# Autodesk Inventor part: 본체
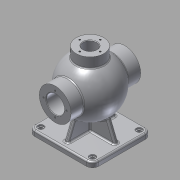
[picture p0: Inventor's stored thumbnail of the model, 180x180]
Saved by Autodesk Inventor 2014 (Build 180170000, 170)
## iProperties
Created: 2015-10
Part Number: 본체
Material: Aluminum 6061
Document SubType Name: Modeling
Designer: youjin08
Density: 2.71 g/cm^3
Appearance: Aluminum - Flat
Mass: 1509.57 g
Surface Area: 1153.7 cm^2
Volume: 557.037 cm^3
Author: youjin08
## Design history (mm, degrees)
sketch "Sketch1"
  geometry: L1 (-62.5, -57.5)-(62.5, -57.5); L2 (62.5, -57.5)-(62.5, 57.5); L3 (62.5, 57.5)-(-62.5, 57.5); L4 (-62.5, 57.5)-(-62.5, -57.5); L5 (-62.5, -57.5)-(62.5, 57.5); L6 (62.5, -57.5)-(-62.5, 57.5); 1 further point
  constraints: 12 end point, 2 midpoint, 2 parallel, 1 horizontal, 1 perpendicular
  dimensions: "d0" = 125 distance of L3.end L2.end; "d1" = 115 distance of L2.end L1.end
extrude "Extrusion1" new body sketch "Sketch1" distance "d2" = 10; taper "d3" = 0 deg
fillet "Fillet1" dims "d4" = 12
sketch "Sketch2"
  geometry: C1 r 6 at (-50.5, 45.5); C2 r 6 at (-50.5, -45.5); C3 r 6 at (50.5, 45.5); C4 r 6 at (50.5, -45.5); A1 r 12 centre (50.5, 45.5) between (62.5, 45.5) and (50.5, 57.5) reference; A2 r 12 centre (-50.5, 45.5) between (-50.5, 57.5) and (-62.5, 45.5) reference; A3 r 12 centre (-50.5, -45.5) between (-62.5, -45.5) and (-50.5, -57.5) reference; A4 r 12 centre (50.5, -45.5) between (50.5, -57.5) and (62.5, -45.5) reference; 1 further point
  constraints: 4 centre point, 4 coincident
  dimensions: "d5" = 12 diameter of C1; "d6" = 12 diameter of C2; "d7" = 12 diameter of C3; "d8" = 12 diameter of C4
extrude "Extrusion2" cut sketch "Sketch2" distance "d9" = 3; taper "d10" = 0 deg
sketch "Sketch3"
  geometry: C1 r 6 at (0, 0) reference; C2 r 6 at (0, 91) reference; C3 r 6 at (101, 91) reference; C4 r 6 at (101, 0) reference; C5 r 4 at (0, 0); C6 r 4 at (0, 91); C7 r 4 at (101, 91); C8 r 4 at (101, 0); 1 further point
  constraints: 4 centre point, 4 coincident
  dimensions: "d11" = 8 diameter of C5; "d12" = 8 diameter of C6; "d13" = 8 diameter of C7; "d14" = 8 diameter of C8
extrude "Extrusion3" cut sketch "Sketch3" stored distance "d15" = 3; taper "d16" = 0 deg
sketch "Sketch4"
  geometry: L1 (50.5, 57.5)-(-50.5, 57.5) reference; L2 (-62.5, 45.5)-(-62.5, -45.5) reference; L3 (-50.5, -57.5)-(50.5, -57.5) reference; L4 (62.5, -45.5)-(62.5, 45.5) reference; C1 r 6 at (50.5, 45.5) reference; C2 r 6 at (-50.5, 45.5) reference; C3 r 6 at (-50.5, -45.5) reference; C4 r 6 at (50.5, -45.5) reference; A1 r 12 centre (50.5, 45.5) between (62.5, 45.5) and (50.5, 57.5) reference; A2 r 12 centre (-50.5, 45.5) between (-50.5, 57.5) and (-62.5, 45.5) reference; A3 r 12 centre (-50.5, -45.5) between (-62.5, -45.5) and (-50.5, -57.5) reference; A4 r 12 centre (50.5, -45.5) between (50.5, -57.5) and (62.5, -45.5) reference; 1 further point
sketch "Sketch5"
  geometry: L1 (0, 32)-(0, 138); A1 r 53 centre (0, 85) between (0, 32) and (0, 138); 1 further point
  constraints: 2 end point, 2 point on circle, 1 centre point, 1 vertical alignment
  dimensions: "d17" = 53 radius of A1; "d18" = 85 distance of point (0, 0) A1.centre
revolve "Revolution1" sketch "Sketch5" stored, may be unused: angle "d19" = 90 deg
sketch "Sketch7"
  geometry: C1 r 53 at (0, 85) reference; C2 r 31 at (0, 85); 1 further point
  constraints: 1 centre point, 1 coincident
  dimensions: "d20" = 62 diameter of C2
extrude "Extrusion4" join sketch "Sketch7" stored distance "d21" = 136; taper "d22" = 0 deg
sketch "Sketch8"
  geometry: L1 (0, 42)-(0, 128); C1 r 53 at (0, 85) reference; A1 r 43 centre (0, 85) between (0, 42) and (0, 128); 1 further point
  constraints: 2 end point, 2 point on circle, 1 centre point, 1 coincident, 1 vertical
  dimensions: "d23" = 43 radius of A1
revolve "Revolution2" sketch "Sketch8" stored, may be unused: angle "d24" = 90 deg
sketch "Sketch9"
  geometry: C1 r 31 at (0, 0) reference; C2 r 17.5 at (0, 0); 1 further point
  constraints: 1 centre point, 1 coincident
  dimensions: "d25" = 35 diameter of C2
extrude "Extrusion5" cut sketch "Sketch9" stored distance "d26" = 136; taper "d27" = 0 deg
workplane "Work Plane1"
sketch "Sketch10"
  geometry: C1 r 27 at (0, 0); 1 further point
  constraints: 1 centre point, 1 coincident
  dimensions: "d29" = 54 diameter of C1
extrude "Extrusion6" join sketch "Sketch10" stored distance "d30" = 136; taper "d31" = 0 deg
sketch "Sketch11"
  geometry: C1 r 27 at (0, 0) reference; C2 r 13 at (0, 0)
  constraints: 1 centre point, 1 coincident
  dimensions: "d32" = 26 diameter of C2
extrude "Extrusion7" cut sketch "Sketch11" stored distance "d33" = 136; taper "d34" = 0 deg
sketch "Sketch13"
  geometry: C1 r 17.5 at (0, 0) reference; C2 r 31 at (0, 0) reference; A1 r 22.5 centre (0, 0) between (0, 22.5) and (-22.5, 0); 3 further points
  constraints: 4 point on circle, 2 horizontal alignment, 2 vertical alignment, 1 centre point, 1 coincident
  dimensions: "d35" = 45 diameter of A1
hole "Hole1" sketch "Sketch13" at (0, 22.5), (-22.5, 0), (0, -22.5), (22.5, 0) diameter "d36" = 3.242; stored, may be unused: countersink angle "d40" = 90 deg, drill point angle "d42" = 118 deg; dims "d37" = 12, "d38" = 4, "d39" = 2, "d41" = 15
sketch "Sketch15"
  geometry: C1 r 17.5 at (0, 0) reference; C2 r 31 at (0, 0) reference; A1 r 24 centre (0, 0) between (0, 24) and (-24, 0); 3 further points
  constraints: 4 point on circle, 2 horizontal alignment, 2 vertical alignment, 1 centre point, 1 coincident
  dimensions: "d43" = 48 diameter of A1
sketch "Sketch16"
  geometry: C1 r 13 at (0, 0) reference; C2 r 27 at (0, 0) reference; A1 r 20 centre (0, 0) between (0, 20) and (20, 0); 2 further points
  constraints: 4 point on circle, 2 horizontal alignment, 2 vertical alignment, 1 centre point, 1 coincident
  dimensions: "d51" = 40 diameter of A1
hole "Hole3" sketch "Sketch16" at (0, 20), (-20, 0), (0, -20), (20, 0) diameter "d52" = 3.242; stored, may be unused: countersink angle "d56" = 90 deg, drill point angle "d58" = 118 deg; dims "d53" = 9, "d54" = 4, "d55" = 2, "d57" = 11
sketch "Sketch17"
  geometry: L1 (-56.5, 10)-(-44.5, 10) reference; L2 (-62.5, 10)-(-50.5, 10) reference; L3 (50.5, 10)-(62.5, 10) reference; L4 (44.5, 10)-(56.5, 10) reference; L5 (-37.379, 47.426)-(-52.5, 10); L6 (37.379, 47.426)-(52.5, 10); L7 (-62.5, 0)-(-62.5, 10) reference; L8 (62.5, 10)-(62.5, 0) reference; A1 r 53 centre (0, 85) between (-27, 130.607) and (27, 130.607) reference; A2 r 53 centre (0, 85) between (-27, 130.607) and (27, 130.607) reference; 1 further point
  constraints: 4 end point, 2 point on circle, 2 point on line
  dimensions: "d59" = 22 deg angle of L7 L5; "d60" = 10 distance from line of L7 L5.end; "d61" = 22 deg angle of L8 L6; "d62" = 10 distance from line of L8 L6.end
sketch "Sketch18"
  geometry: L1 (50.5, 57.5)-(-50.5, 57.5) reference; L2 (-62.5, 45.5)-(-62.5, -45.5) reference; L3 (-50.5, -57.5)-(50.5, -57.5) reference; L4 (62.5, -45.5)-(62.5, 45.5) reference; L5 (-4, -45.5)-(4, -45.5); L6 (4, -45.5)-(4, 45.5); L7 (4, 45.5)-(-4, 45.5); L8 (-4, 45.5)-(-4, -45.5); L9 (-4, -45.5)-(4, 45.5); L10 (4, -45.5)-(-4, 45.5); L11 (-50.5, -4)-(50.5, -4); L12 (50.5, -4)-(50.5, 4); L13 (50.5, 4)-(-50.5, 4); L14 (-50.5, 4)-(-50.5, -4); L15 (-50.5, -4)-(50.5, 4); L16 (50.5, -4)-(-50.5, 4); C1 r 6 at (50.5, -45.5) reference; C2 r 6 at (-50.5, -45.5) reference; C3 r 6 at (-50.5, 45.5) reference; C4 r 6 at (50.5, 45.5) reference; A1 r 12 centre (50.5, 45.5) between (62.5, 45.5) and (50.5, 57.5) reference; A2 r 12 centre (-50.5, 45.5) between (-50.5, 57.5) and (-62.5, 45.5) reference; A3 r 12 centre (-50.5, -45.5) between (-62.5, -45.5) and (-50.5, -57.5) reference; A4 r 12 centre (50.5, -45.5) between (50.5, -57.5) and (62.5, -45.5) reference; 1 further point
  constraints: 24 end point, 4 midpoint, 4 parallel, 2 horizontal, 2 perpendicular
  dimensions: "d63" = 8 distance of L7.end L6.end; "d64" = 91 distance of L6.end L5.end; "d65" = 101 distance of L13.end L12.end; "d66" = 8 distance of L12.end L11.end
fillet "Fillet4" dims "d77" = 3
workplane "Work Plane2"
sketch "Sketch20"
  geometry: C1 r 17.5 at (0, 0) reference; C2 r 18.5 at (0, 0); 1 further point
  constraints: 1 centre point, 1 coincident
  dimensions: "d79" = 37 diameter of C2
sketch "Sketch21"
  geometry: 1 further point
extrude "Extrusion10" join sketch "Sketch20" distance "d80" = 1.75; taper "d81" = 0 deg
sketch "Sketch22"
  geometry: 1 further point
sketch "Sketch23"
  geometry: C1 r 17.5 at (0, 0) reference; C2 r 18.5 at (0, 0); 1 further point
  constraints: 1 centre point, 1 coincident
  dimensions: "d82" = 37 diameter of C2
extrude "Extrusion11" cut sketch "Sketch23" distance "d83" = 1.75; taper "d84" = 0 deg
hole "Hole4" sketch "Sketch15" diameter "d85" = 3.242; stored, may be unused: countersink angle "d89" = 90 deg, drill point angle "d91" = 118 deg; dims "d86" = 16, "d87" = 4, "d88" = 2, "d90" = 19
chamfer "Chamfer1" distance "d92" = 1; stored, may be unused: second distance "d93" = 2, angle "d94" = 45 deg
workplane "Work Plane3"
sketch "Sketch24"
  geometry: 1 further point
sketch "Sketch25"
  geometry: L1 (-27, 150)-(27, 150) reference; L2 (-27, 150)-(-27, 132.286) reference; 2 further points
  constraints: 1 other
  dimensions: "d96" = 10 distance from line of point (0, 140) L1; "d97" = 27 distance from line of L2 point (0, 140)
emboss "Emboss1" sketch "Sketch25" dims "d98" = 0.5, "d99" = 0
fillet "Fillet5" dims "d100" = 3
sketch "Sketch26"
  geometry: L1 (-4, -4)-(4, -4); L2 (4, -4)-(4, 4); L3 (4, 4)-(-4, 4); L4 (-4, 4)-(-4, -4); L5 (-4, -4)-(4, 4); L6 (4, -4)-(-4, 4); 1 further point
  constraints: 12 end point, 2 midpoint, 2 parallel, 1 horizontal, 1 perpendicular
  dimensions: "d101" = 8 distance of L3.end L2.end; "d102" = 8 distance of L2.end L1.end
extrude "Extrusion12" join sketch "Sketch26" stored distance "d103" = 8; taper "d104" = 0 deg
feature "Rib1" dims "d105" = 1, "d106" = 8, "d107" = 0, "d108" = 0, "d109" = 1, "d110" = 1
feature "Rib2" dims "d111" = 1, "d112" = 8, "d113" = 0, "d114" = 0, "d115" = 1, "d116" = 1
sketch "Sketch27"
  geometry: L1 (-57.5, 10)-(-45.5, 10) reference; L2 (45.5, 10)-(57.5, 10) reference; L3 (-47.5, 10)-(-33.719, 44.109); L4 (47.5, 10)-(33.719, 44.109); L5 (-57.5, 0)-(-57.5, 10) reference; L6 (57.5, 10)-(57.5, 0) reference; A1 r 53 centre (0, 85) between (42.113, 117.179) and (42.113, 52.821) reference; 1 further point
  constraints: 4 end point, 2 point on circle, 2 point on line
  dimensions: "d117" = 22 deg angle of L5 L3; "d118" = 10 distance from line of L5 L3.start; "d119" = 22 deg angle of L6 L4; "d120" = 10 distance from line of L6 L4.start
feature "Rib3" dims "d121" = 1, "d122" = 8, "d123" = 0, "d124" = 0, "d125" = 1, "d126" = 1
feature "Rib4" dims "d127" = 1, "d128" = 8, "d129" = 0, "d130" = 0, "d131" = 1, "d132" = 1
fillet "Fillet6" dims "d133" = 3
fillet "Fillet7" dims "d134" = 3
sketch "Sketch28"
  geometry: 1 further point
body "Solid1"
other parameters: "d78" = -16, "d95" = -27.5
